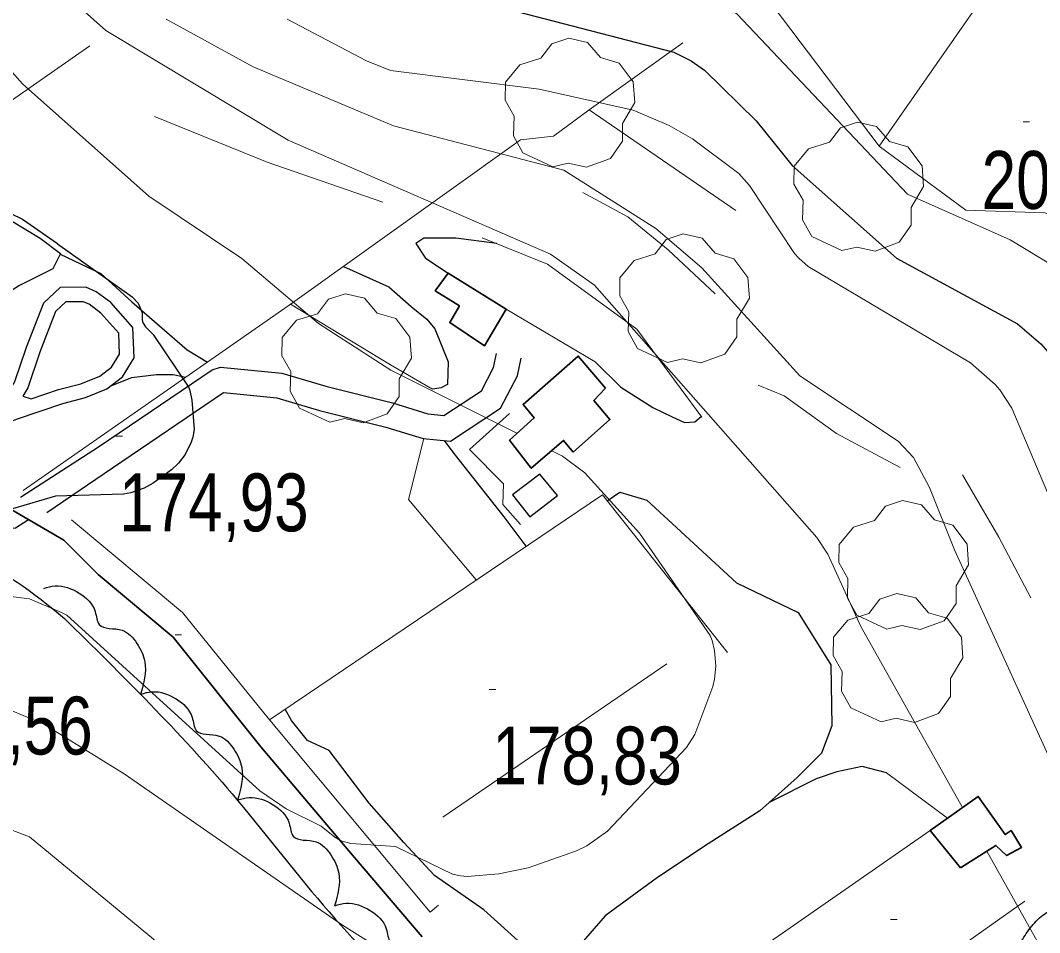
# Model space of a CAD drawing. Extents: x 483847 to 488453, y 4383581 to 4386795.
# Drawn here: x 485127.1 to 485281.1, y 4386177.1 to 4386315 of the extents above; entities that cross this region are included whole.
import ezdxf

# ---------------------------------------------------------------- set-up
doc = ezdxf.new("R2010")
doc.units = 0
doc.header["$LTSCALE"] = 3.8
doc.linetypes.add('LONG_DASHED', pattern=[7.5, 6, -1.5])
doc.linetypes.add('MEDIUM_DASHED', pattern=[4.5, 3, -1.5])
for name, color, linetype, lineweight in [('21', 7, 'Continuous', 25), ('25', 7, 'LONG_DASHED', 25), ('27', 7, 'Continuous', 25), ('29', 7, 'Continuous', 13), ('38', 7, 'Continuous', 25), ('47', 7, 'Continuous', 35), ('51', 7, 'Continuous', 13), ('6', 7, 'Continuous', 35), ('7', 7, 'Continuous', 13), ('8', 7, 'Continuous', 25), ('9', 7, 'Continuous', 13)]:
    doc.layers.add(name, color=color, linetype=linetype, lineweight=lineweight)

msp = doc.modelspace()

# ---------------------------------------------------------------- linework, layer by layer
at = {"layer": '21'}
msp.add_lwpolyline([(485204.06, 4386239.98), (485208.24, 4386243.23), (485205.57, 4386246.43), (485201.43, 4386243.32)], close=True, dxfattribs=at)
at = {"layer": '25'}
for points in [[(485121.6, 4386286.68), (485125.74, 4386284.73), (485130.04, 4386282.11), (485133.13, 4386279.79), (485131.98, 4386277.46), (485126.95, 4386274.94), (485118.65, 4386269.8), (485104.91, 4386261.25), (485101.1, 4386259.19), (485095.76, 4386258.01), (485092.86, 4386258.18), (485087.24, 4386260.12), (485082.3, 4386262.33), (485080.57, 4386262.97), (485077.97, 4386264.8), (485077.43, 4386267.43), (485077.65, 4386270.72)], [(485199.08, 4386281.29), (485192.89, 4386282.13), (485188.06, 4386282.1), (485186.82, 4386281.29), (485188.28, 4386279.11), (485191.72, 4386276.83)], [(485133.09, 4386279.71), (485139.24, 4386276.79), (485143.92, 4386272.48), (485152.26, 4386265.21), (485155.35, 4386263.37)], [(485175.92, 4386277.85), (485182.73, 4386274.75), (485186.13, 4386271.78), (485188.5, 4386269.89), (485189.72, 4386268.39), (485191.73, 4386263.4), (485191.63, 4386260.01), (485190.67, 4386259.49), (485189.37, 4386259.28)], [(485213.96, 4386263.41), (485217.83, 4386259.59), (485222.63, 4386256.54), (485225.56, 4386255.1), (485227.46, 4386254.27), (485229.02, 4386254.35), (485229.98, 4386255.16)], [(485152.01, 4386261.04), (485150.15, 4386261.47), (485147.65, 4386261.43), (485143.87, 4386261.02), (485140.66, 4386259.74)], [(485203.5, 4386235.53), (485200.19, 4386239.97), (485192.63, 4386249.57), (485191.15, 4386251.53)], [(485215.76, 4386242.41), (485217.65, 4386243.71), (485221.75, 4386242.52), (485235.32, 4386230.02), (485239.36, 4386228.02), (485244.64, 4386225.53), (485249.56, 4386217.62), (485249.72, 4386208.37), (485248.14, 4386204.25), (485244.45, 4386200.55), (485238.8, 4386195.51), (485231, 4386190.55), (485223.38, 4386185.46), (485215.47, 4386179.64), (485210.8, 4386174.3)], [(485202.32, 4386175.87), (485197.09, 4386180.58), (485189.63, 4386185.73), (485185.01, 4386190.75), (485179.8, 4386196.7), (485173.74, 4386204.67), (485170.46, 4386206.16), (485168.02, 4386209.21), (485167.09, 4386210.92)], [(485257.99, 4386201.27), (485254.29, 4386202.23), (485250.47, 4386201.44), (485247.34, 4386200.39), (485240.24, 4386196.79)]]:
    msp.add_lwpolyline(points, dxfattribs=at)
at = {"layer": '27'}
for points in [[(484700.18, 4386195.41), (484750.6, 4386216.22), (484776.67, 4386228), (484779.62, 4386225.05), (484778.78, 4386222.11), (484767.42, 4386211.17), (484761.53, 4386201.49), (484762.8, 4386188.87), (484767, 4386176.67), (484776.67, 4386171.2), (484788.03, 4386171.62), (484796.86, 4386188.03), (484811.16, 4386231.78), (484821.67, 4386263.34), (484838.91, 4386286.48), (484868.77, 4386322.24), (484889.8, 4386336.55), (484901.57, 4386337.81), (484912.09, 4386332.76), (484919.24, 4386332.76), (484928.07, 4386336.55), (484929.75, 4386336.55), (484935.22, 4386336.55), (484960.45, 4386328.13), (484990.73, 4386305.83), (485012.18, 4386295.73), (485037.41, 4386278.06), (485058.02, 4386260.39), (485061.38, 4386254.92), (485060.54, 4386248.19), (485059.28, 4386246.09), (485054.23, 4386246.93), (485039.93, 4386264.18), (485027.32, 4386274.7), (485013.02, 4386281.43), (485005.87, 4386280.17), (485002.5, 4386272.17), (485003.77, 4386259.55), (485026.05, 4386241.46), (485035.31, 4386235.15), (485042.88, 4386225.89), (485046.66, 4386209.06), (485049.61, 4386199.81), (485055.91, 4386190.97), (485066.85, 4386188.45), (485075.26, 4386188.87), (485091.66, 4386197.7), (485095.86, 4386206.54), (485096.29, 4386218.74), (485100.07, 4386226.31), (485108.9, 4386233.89), (485118.57, 4386233.89), (485133.71, 4386224.63)], [(485130.59, 4386229.17), (485132.33, 4386229.54), (485135.96, 4386228.45), (485138.37, 4386225.65), (485138.98, 4386223.69), (485142.44, 4386222.84), (485144.66, 4386220.85), (485145.87, 4386218.08), (485145.24, 4386213.16)], [(485133.71, 4386224.63), (485159.06, 4386198.09), (485188.19, 4386166.36), (485207.92, 4386153.41), (485233.17, 4386127.84), (485249.02, 4386109.71), (485250.32, 4386104.85), (485249.99, 4386103.55), (485244.17, 4386106.47), (485239.31, 4386111), (485236.73, 4386111.65), (485233.81, 4386107.44), (485232.52, 4386102.26), (485233.17, 4386099.02), (485238.02, 4386087.04), (485266.5, 4386058.55), (485267.47, 4386055.96), (485266.17, 4386055.64), (485261.64, 4386057.26), (485233.81, 4386088.99), (485220.55, 4386101.29), (485207.28, 4386106.47), (485205.01, 4386106.47), (485201.13, 4386105.82), (485194.33, 4386097.4), (485191.34, 4386093.38)], [(485145.25, 4386213.17), (485146.98, 4386213.54), (485150.62, 4386212.44), (485153.03, 4386209.65), (485153.64, 4386207.69), (485157.09, 4386206.84), (485159.32, 4386204.85), (485160.53, 4386202.08), (485159.9, 4386197.16)], [(485159.91, 4386197.17), (485161.64, 4386197.54), (485165.27, 4386196.45), (485167.69, 4386193.65), (485168.3, 4386191.69), (485171.76, 4386190.84), (485173.98, 4386188.86), (485175.19, 4386186.09), (485174.56, 4386181.17)], [(485174.57, 4386181.17), (485176.31, 4386181.55), (485179.94, 4386180.46), (485182.36, 4386177.67), (485182.98, 4386175.71), (485186.43, 4386174.86), (485188.66, 4386172.88), (485189.88, 4386170.11), (485189.25, 4386165.19)]]:
    msp.add_spline(points, degree=3, dxfattribs=at)
at = {"layer": '29'}
for points in [[(485207.55, 4386292.92), (485203.01, 4386295.04), (485201.6, 4386297.58), (485201.7, 4386300.56), (485200.33, 4386302.97), (485200.37, 4386305.72), (485202.53, 4386308.32), (485205.72, 4386309.32), (485207.37, 4386311.51), (485209.94, 4386312.34), (485212.8, 4386311.69), (485214.75, 4386309.42), (485217.56, 4386308.6), (485219.69, 4386305.75), (485219.93, 4386302.62), (485218.05, 4386299.47), (485218.05, 4386296.79), (485216.23, 4386294.18), (485212.61, 4386292.84), (485209.84, 4386293.47)], [(485251.2, 4386280.23), (485246.66, 4386282.35), (485245.25, 4386284.89), (485245.35, 4386287.87), (485243.98, 4386290.28), (485244.02, 4386293.03), (485246.18, 4386295.63), (485249.37, 4386296.63), (485251.02, 4386298.82), (485253.59, 4386299.65), (485256.45, 4386299), (485258.4, 4386296.73), (485261.21, 4386295.91), (485263.34, 4386293.06), (485263.58, 4386289.93), (485261.7, 4386286.78), (485261.7, 4386284.1), (485259.88, 4386281.49), (485256.26, 4386280.15), (485253.49, 4386280.78)], [(485224.86, 4386263.33), (485220.32, 4386265.45), (485218.91, 4386267.99), (485219.01, 4386270.97), (485217.64, 4386273.38), (485217.68, 4386276.13), (485219.84, 4386278.73), (485223.03, 4386279.73), (485224.68, 4386281.92), (485227.25, 4386282.75), (485230.11, 4386282.1), (485232.06, 4386279.83), (485234.87, 4386279.01), (485237, 4386276.16), (485237.24, 4386273.03), (485235.36, 4386269.88), (485235.36, 4386267.2), (485233.54, 4386264.59), (485229.92, 4386263.25), (485227.15, 4386263.88)], [(485173.81, 4386254.3), (485169.27, 4386256.42), (485167.86, 4386258.96), (485167.96, 4386261.94), (485166.59, 4386264.35), (485166.63, 4386267.1), (485168.79, 4386269.7), (485171.98, 4386270.7), (485173.63, 4386272.89), (485176.2, 4386273.72), (485179.06, 4386273.07), (485181.01, 4386270.8), (485183.82, 4386269.98), (485185.95, 4386267.13), (485186.19, 4386264), (485184.31, 4386260.85), (485184.31, 4386258.17), (485182.49, 4386255.56), (485178.87, 4386254.22), (485176.1, 4386254.85)], [(485258, 4386223.02), (485253.46, 4386225.14), (485252.05, 4386227.68), (485252.15, 4386230.66), (485250.78, 4386233.07), (485250.82, 4386235.82), (485252.98, 4386238.42), (485256.17, 4386239.42), (485257.82, 4386241.61), (485260.39, 4386242.44), (485263.25, 4386241.79), (485265.2, 4386239.52), (485268.01, 4386238.7), (485270.14, 4386235.85), (485270.38, 4386232.72), (485268.5, 4386229.57), (485268.5, 4386226.89), (485266.68, 4386224.28), (485263.06, 4386222.94), (485260.29, 4386223.57)], [(485257.14, 4386208.97), (485252.6, 4386211.09), (485251.19, 4386213.63), (485251.29, 4386216.61), (485249.92, 4386219.02), (485249.96, 4386221.77), (485252.12, 4386224.37), (485255.31, 4386225.37), (485256.96, 4386227.56), (485259.53, 4386228.39), (485262.39, 4386227.74), (485264.34, 4386225.47), (485267.15, 4386224.65), (485269.28, 4386221.8), (485269.52, 4386218.67), (485267.64, 4386215.52), (485267.64, 4386212.84), (485265.82, 4386210.23), (485262.2, 4386208.89), (485259.43, 4386209.52)]]:
    msp.add_lwpolyline(points, close=True, dxfattribs=at)
at = {"layer": '38'}
for points in [[(485112.48, 4386247.26), (485116.82, 4386249.37), (485119.93, 4386251.44), (485123.22, 4386253.43), (485126.48, 4386254.76), (485133.48, 4386257.14), (485136.9, 4386258.04), (485140.14, 4386259.35), (485142.51, 4386261.14), (485144.25, 4386264.03), (485144.08, 4386268.6), (485140.72, 4386272.37), (485138.54, 4386274.01), (485136.98, 4386274.69), (485133.1, 4386274.67), (485130.54, 4386272.31), (485127.94, 4386265.61), (485126.18, 4386260.4), (485125.52, 4386259.24), (485122.33, 4386255.41)], [(485127.07, 4386242.94), (485138.87, 4386250.55), (485156.06, 4386262.21), (485157.33, 4386262.61), (485166.57, 4386261.73), (485173.25, 4386259.74), (485183.33, 4386257.22), (485188.66, 4386255.55), (485191.08, 4386255.33), (485196.74, 4386259.06), (485198.59, 4386262.58), (485199.01, 4386264.68)], [(485131.07, 4386240.63), (485141, 4386247.41), (485157.74, 4386258.77), (485157.74, 4386258.77), (485165.84, 4386257.99), (485172.25, 4386256.08), (485182.3, 4386253.56), (485187.92, 4386251.81), (485192.06, 4386251.44), (485199.64, 4386256.43), (485202.2, 4386261.3), (485202.73, 4386263.95)]]:
    msp.add_lwpolyline(points, dxfattribs=at)
at = {"layer": '38', "linetype": 'MEDIUM_DASHED'}
msp.add_lwpolyline([(485128.69, 4386257.81), (485132.85, 4386259.22), (485136.21, 4386260.11), (485139.06, 4386261.26), (485140.86, 4386262.62), (485142.05, 4386264.6), (485141.94, 4386267.74), (485139.24, 4386270.76), (485137.44, 4386272.12), (485136.53, 4386272.51), (485133.95, 4386272.5), (485132.38, 4386271.05), (485129.98, 4386264.87), (485128.17, 4386259.51), (485127.44, 4386258.22)], close=True, dxfattribs=at)
msp.add_lwpolyline([(485082.04, 4386249.77), (485095.45, 4386244.79), (485107.37, 4386241.31), (485119.03, 4386238.78), (485121.83, 4386237.91), (485126.35, 4386238.31), (485128.28, 4386239.57)], dxfattribs=at)
at = {"layer": '38', "linetype": 'LONG_DASHED'}
msp.add_spline([(485240.87, 4386137.62), (485252.25, 4386143.99), (485257.41, 4386147.54), (485262.4, 4386152.24), (485268.48, 4386156.78), (485272.15, 4386159.88), (485276.05, 4386164.41), (485279.2, 4386169.17), (485277.73, 4386172.69), (485279.28, 4386177.24), (485283.25, 4386180.58), (485286.56, 4386180.54), (485291.92, 4386177.73), (485292.67, 4386176.17)], degree=3, dxfattribs=at)
at = {"layer": '47'}
for points in [[(485200.48, 4386271.38), (485197.2, 4386265.82), (485191.96, 4386269.36), (485193.41, 4386271.88), (485189.76, 4386274.16), (485191.72, 4386276.83)], [(485215.52, 4386259.46), (485211.37, 4386264.28), (485203.03, 4386256.99), (485204.72, 4386254.94), (485200.99, 4386251.59), (485204.28, 4386247.34), (485209.17, 4386251.53), (485210.62, 4386249.78), (485216.17, 4386254.7), (485213.75, 4386257.56)], [(485269.17, 4386186.92), (485264.55, 4386192.57), (485271.83, 4386197.7), (485275.91, 4386191.95), (485276.81, 4386192.54), (485278.39, 4386190.01), (485276.13, 4386188.76), (485274.5, 4386190.3)]]:
    msp.add_lwpolyline(points, close=True, dxfattribs=at)
at = {"layer": '51'}
for p, q in [((485137.58, 4386311.22), (485117.83, 4386297.43)), ((485213.03, 4386301.53), (485235.19, 4386286.28)), ((485200.48, 4386271.38), (485213.96, 4386263.41)), ((485224.79, 4386217.78), (485190.9, 4386194.57)), ((485267.17, 4386194.42), (485257.99, 4386201.27)), ((485264.55, 4386192.57), (485222.6, 4386163.42)), ((485238.34, 4386153.36), (485278.87, 4386181.85))]:
    msp.add_line(p, q, dxfattribs=at)
for points in [[(485360.52, 4386445.68), (485360.33, 4386445.34), (485348.42, 4386428.36), (485322.59, 4386388.81), (485319.46, 4386386.05), (485317.63, 4386380.46), (485316.57, 4386378.09), (485313.86, 4386376.72), (485313, 4386375.75), (485295.93, 4386352.08), (485256.87, 4386296.04), (485242.27, 4386315.34), (485232.39, 4386328.18), (485227.86, 4386330.69)], [(485227.2, 4386311.63), (485213.01, 4386301.51), (485207.66, 4386297.54), (485202.67, 4386297), (485168.2, 4386272.32), (485127.5, 4386243.96)], [(485147.35, 4386300.51), (485164.35, 4386293.62), (485181.82, 4386287.56)], [(485256.87, 4386296.04), (485269.97, 4386286.36), (485281.92, 4386285.97), (485295.08, 4386280.86), (485300.63, 4386277.71), (485305.31, 4386274.34), (485306.9, 4386271.08)], [(485212.07, 4386289), (485218.88, 4386285.32), (485224.95, 4386280.33), (485232.09, 4386273.7)], [(485230.06, 4386255.04), (485220.23, 4386268.35), (485206.74, 4386278.17), (485196.86, 4386282.19)], [(485167.9, 4386272.12), (485183.02, 4386262.99), (485189.37, 4386259.28)], [(485260.02, 4386247.43), (485250.43, 4386252.56), (485242.48, 4386258.3), (485238.55, 4386259.87)], [(485202.67, 4386238.8), (485199.98, 4386241.83), (485200.08, 4386244.99), (485194.95, 4386250.19), (485200.97, 4386255.6)], [(485195.96, 4386230.44), (485185.72, 4386242.6), (485188.04, 4386251.81)], [(485269.46, 4386246.35), (485274.96, 4386236.92), (485279.79, 4386227.73)], [(485233.93, 4386219.48), (485215.03, 4386243.32), (485164.71, 4386209.31)], [(485134.81, 4386239.51), (485151.56, 4386225.5), (485164.52, 4386209.53), (485189.02, 4386180.23), (485190.27, 4386181.27)]]:
    msp.add_lwpolyline(points, dxfattribs=at)
at = {"layer": '6'}
msp.add_lwpolyline([(485125.75, 4386241.04), (485133.62, 4386236.48), (485138.8, 4386231.28), (485150.15, 4386221.79), (485163.42, 4386205.22), (485177.27, 4386188.83), (485187.8, 4386176.49)], dxfattribs=at)
at = {"layer": '7'}
for p, q in [((485278.6, 4386299.72), (485279.6, 4386299.72)), ((485141.5, 4386252.16), (485142.5, 4386252.16)), ((485150.44, 4386222.13), (485151.44, 4386222.13)), ((485197.91, 4386213.89), (485198.91, 4386213.89)), ((485258.59, 4386179.1), (485259.59, 4386179.1))]:
    msp.add_line(p, q, dxfattribs=at)
at = {"layer": '8'}
for points in [[(485084.04, 4386446.21), (485134.06, 4386359.92), (485146.97, 4386342.39), (485156.63, 4386333.56), (485165.58, 4386327.63), (485177.02, 4386322.95), (485225.81, 4386310.24), (485228.47, 4386308.93), (485230.46, 4386307.5), (485238.27, 4386299.85), (485243.73, 4386293.13), (485259.47, 4386279.08), (485277.76, 4386269.18), (485281.27, 4386266.13), (485285.15, 4386261.7), (485320.46, 4386180.26), (485356.58, 4386136.4)], [(485112.27, 4386292.28), (485127.37, 4386284.97), (485132.66, 4386281.33), (485132.68, 4386281.28), (485143.97, 4386273.26), (485144.89, 4386272.28), (485145.48, 4386270.83), (485145.49, 4386269.75), (485145.54, 4386269.51), (485145.6, 4386269.29), (485145.99, 4386268.69), (485147.15, 4386267.54), (485152.5, 4386259.54), (485152.66, 4386259.07), (485152.98, 4386257.6), (485153.32, 4386253.18)], [(485153.32, 4386253.18), (485153.13, 4386252.03), (485152.89, 4386251.29), (485151.97, 4386249.42), (485150.95, 4386248.09), (485149.91, 4386247.08), (485147.15, 4386245.05), (485145.76, 4386244.34), (485143.76, 4386243.63), (485142.67, 4386243.42), (485132.38, 4386243.1), (485125.89, 4386241.21)]]:
    msp.add_lwpolyline(points, dxfattribs=at)
at = {"layer": '9'}
for points in [[(485202.12, 4386252.61), (485183.03, 4386262.17), (485172.13, 4386269.22), (485160.54, 4386279.02), (485146.5, 4386288.48), (485127.37, 4386305.46), (485111.77, 4386323.09), (485085.49, 4386344.69), (485083.4, 4386346.91), (485081.34, 4386349.86), (485079.07, 4386354.73), (485074.86, 4386371.45), (485072.29, 4386383.86), (485055.76, 4386446.27)], [(485064.13, 4386446.25), (485097.01, 4386357.83), (485120.33, 4386331.03), (485139.99, 4386313.52), (485167.53, 4386296.94), (485207.17, 4386279.69), (485213.86, 4386275.01), (485247.44, 4386236.88), (485249.1, 4386234.36), (485254.11, 4386223.4), (485269.44, 4386196.02)], [(485110.74, 4386410.89), (485142.7, 4386360.37), (485146.68, 4386356.05), (485172.29, 4386334.17), (485182.77, 4386328.09), (485189.41, 4386325.55), (485199.8, 4386323.3), (485224.77, 4386320.95), (485229.46, 4386319.63), (485231.86, 4386318.51), (485235.42, 4386315.98), (485261.16, 4386288.79), (485276.68, 4386281.87), (485285.82, 4386276.3)], [(485284.25, 4386199.84), (485268.23, 4386234.98), (485264.49, 4386244.43), (485262.05, 4386248.95), (485259.72, 4386251.4), (485244.86, 4386261.31), (485230.08, 4386277.64), (485223.11, 4386283.6), (485209.18, 4386292.4), (485183.44, 4386299.09), (485162.23, 4386308.02), (485149.11, 4386315.25)], [(485167.38, 4386315.25), (485179.38, 4386308.92), (485182.98, 4386307.48), (485205.46, 4386304.65), (485219.67, 4386301.48), (485225.13, 4386299.15), (485228.65, 4386297.12), (485235.65, 4386291.89), (485237.25, 4386290.09), (485244.05, 4386279.79), (485244.72, 4386279.07), (485246.14, 4386277.81), (485270.67, 4386263.25), (485274.41, 4386260), (485275.1, 4386259.17), (485276.91, 4386256.39), (485308.82, 4386180.98)], [(484898.31, 4386309.91), (484906.05, 4386309.76), (484908.14, 4386309.39), (484910.74, 4386308.48), (484914.17, 4386306.43), (484983.67, 4386251.79), (485014.88, 4386234.72), (485128.43, 4386191.58), (485164.75, 4386161.61), (485169.72, 4386152.29), (485179.62, 4386142.45), (485180.42, 4386142), (485181.55, 4386141.57), (485182.51, 4386141.37), (485183.68, 4386141.31), (485184.62, 4386141.37), (485186.89, 4386141.88), (485192.18, 4386143.6), (485193.3, 4386143.83), (485195.32, 4386143.88), (485199.77, 4386142.82)], [(485218.03, 4386151.65), (485175.76, 4386178.25), (485142.75, 4386201.11), (485130.62, 4386208.61), (485121.18, 4386212.57), (485068.53, 4386227.33), (485057.07, 4386232.52), (484991.05, 4386270.37)], [(485090.65, 4386232.31), (485128.42, 4386227.6), (485133.3, 4386225.53), (485134.11, 4386225.1), (485163.23, 4386198.55), (485167.26, 4386195.81), (485172.51, 4386193.22), (485174.59, 4386191.56), (485175.09, 4386191.23), (485175.69, 4386190.95), (485176.99, 4386190.6), (485183.76, 4386190.12), (485192.35, 4386185.93), (485193.6, 4386185.69), (485194.6, 4386185.62), (485199.37, 4386186), (485203.82, 4386186.91), (485211.14, 4386189.47), (485212.69, 4386190.22), (485215.8, 4386192.44), (485227.73, 4386205.13), (485228.98, 4386207.09), (485231.7, 4386214.32), (485231.99, 4386215.44), (485232.18, 4386217.41), (485231.95, 4386219.78), (485231.61, 4386221.29), (485231.34, 4386222.06), (485220.66, 4386237.52), (485212.38, 4386246.66), (485208.99, 4386249.17), (485207.37, 4386249.98)], [(485273.13, 4386189.43), (485286.9, 4386164.85), (485288.29, 4386161.17)]]:
    msp.add_lwpolyline(points, dxfattribs=at)

# ---------------------------------------------------------------- texts
at = {"layer": '7', "width": 0.8}
for s, p in [('207,08', (485272.35, 4386286.55)), ('174,93', (485142, 4386237.79)), ('177,56', (485109.36, 4386204.05)), ('178,83', (485198.41, 4386199.52))]:
    msp.add_text(s, height=8.75, dxfattribs=at).set_placement(p)

doc.saveas('drawing.dxf')
